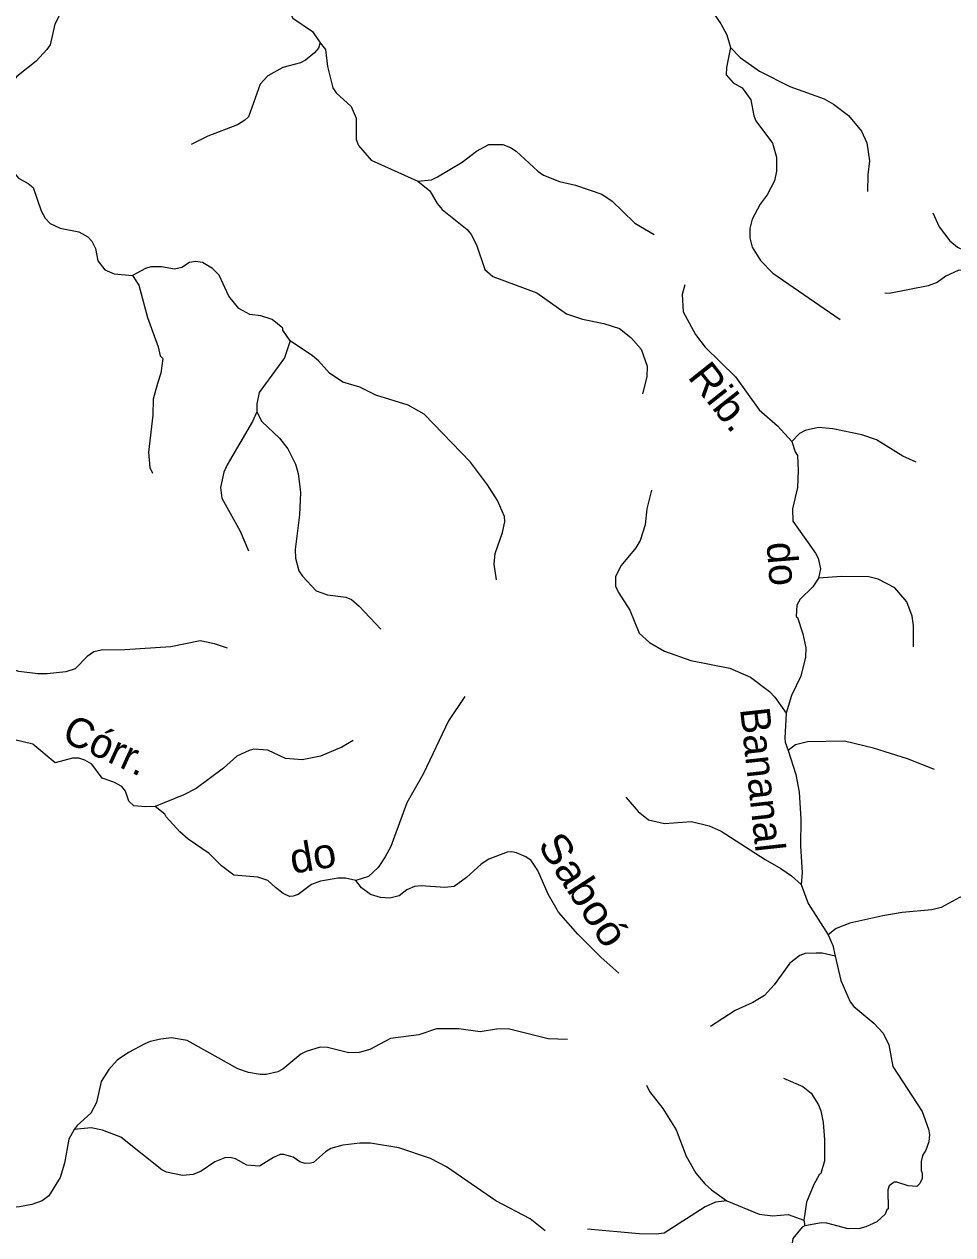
# Model space of a CAD drawing. Extents: x 346.5 to 372.4, y 7400.3 to 7428.2.
# Drawn here: x 350.684 to 353.197, y 7415.488 to 7418.764 of the extents above; entities that cross this region are included whole.
import ezdxf
from ezdxf.enums import TextEntityAlignment as Align

# ---------------------------------------------------------------- set-up
doc = ezdxf.new("R2010")
doc.units = 0
doc.header["$LTSCALE"] = 0.032
doc.layers.add('61', color=7, linetype='Continuous')
doc.layers.add('7', color=7, linetype='Continuous', lineweight=25)

msp = doc.modelspace()

# ---------------------------------------------------------------- linework, layer by layer
at = {"layer": '7'}
for points in [[(350.897, 7418.9228), (350.8692, 7418.8949), (350.8469, 7418.8614), (350.8102, 7418.8312), (350.7911, 7418.8089), (350.7672, 7418.7642), (350.7544, 7418.7085), (350.7457, 7418.6957), (350.717, 7418.6638), (350.6644, 7418.6224), (350.6125, 7418.5604)], [(351.3435, 7418.9146), (351.3768, 7418.8631), (351.3936, 7418.8121), (351.4119, 7418.7802), (351.4645, 7418.7443), (351.4854, 7418.7136)], [(352.4758, 7418.8902), (352.534, 7418.8176), (352.5699, 7418.765), (352.5858, 7418.7355), (352.5963, 7418.7009)], [(351.4854, 7418.7136), (351.4807, 7418.6989), (351.4701, 7418.6861), (351.4454, 7418.6662), (351.4319, 7418.6598), (351.3848, 7418.6471), (351.3442, 7418.624), (351.3227, 7418.6017), (351.2916, 7418.5132), (351.2812, 7418.5044), (351.2621, 7418.4917), (351.1816, 7418.4606), (351.1362, 7418.4383)], [(351.4854, 7418.7136), (351.4999, 7418.695), (351.5052, 7418.6495), (351.5195, 7418.5921), (351.5291, 7418.5778), (351.5689, 7418.5411), (351.5833, 7418.5092), (351.5825, 7418.4518), (351.5888, 7418.4359), (351.6231, 7418.396), (351.7501, 7418.3396)], [(352.5963, 7418.7009), (352.585, 7418.6463), (352.5842, 7418.6272), (352.6033, 7418.6056), (352.6273, 7418.5913), (352.6512, 7418.5594), (352.6591, 7418.5156), (352.6647, 7418.5028), (352.7093, 7418.4423), (352.7205, 7418.404), (352.7205, 7418.3658), (352.7149, 7418.3403), (352.695, 7418.302), (352.6759, 7418.2773), (352.6544, 7418.2367), (352.648, 7418.2112), (352.648, 7418.1857), (352.6544, 7418.1602), (352.6775, 7418.1243), (352.7101, 7418.09), (352.8927, 7417.9649)], [(352.5963, 7418.7009), (352.6225, 7418.6734), (352.6743, 7418.6367), (352.7564, 7418.5953), (352.8496, 7418.5618), (352.8751, 7418.5475), (352.9157, 7418.5172), (352.95, 7418.4742), (352.9652, 7418.4431), (352.9723, 7418.3945), (352.9676, 7418.3562), (352.9668, 7418.3108)], [(350.4957, 7418.4446), (350.5214, 7418.4418), (350.5369, 7418.4359), (350.5616, 7418.4207), (350.6206, 7418.396), (350.6381, 7418.3849), (350.6692, 7418.3474), (350.6955, 7418.3331), (350.709, 7418.3219), (350.7305, 7418.259), (350.7409, 7418.239), (350.7544, 7418.2247), (350.7815, 7418.2119), (350.8326, 7418.2024), (350.8565, 7418.1888), (350.8676, 7418.1769), (350.8772, 7418.157), (350.8835, 7418.1235), (350.9027, 7418.0988), (350.9282, 7418.0884), (350.9779, 7418.0837)], [(351.7501, 7418.3396), (351.7866, 7418.3424), (351.8032, 7418.3506), (351.8694, 7418.3905), (351.9084, 7418.4207), (351.9419, 7418.4383), (351.9801, 7418.4383), (352.0009, 7418.4303), (352.016, 7418.4199), (352.0742, 7418.3658), (352.0901, 7418.3554), (352.1332, 7418.3387), (352.1762, 7418.3283), (352.2479, 7418.3044), (352.2758, 7418.2853), (352.3037, 7418.2582), (352.3372, 7418.2255), (352.389, 7418.1944)], [(351.7501, 7418.3396), (351.7825, 7418.3132), (351.8024, 7418.2789), (351.8152, 7418.2629), (351.8829, 7418.2088), (351.8941, 7418.1952), (351.9084, 7418.1665), (351.9307, 7418.1004), (351.9531, 7418.0812), (352.0718, 7418.0374), (352.1523, 7417.98), (352.1953, 7417.9657), (352.2527, 7417.9537), (352.2957, 7417.9402), (352.326, 7417.9163), (352.3539, 7417.8844), (352.3706, 7417.8382), (352.3698, 7417.8095), (352.3579, 7417.7641)], [(353.1437, 7418.2534), (353.1604, 7418.2159), (353.1899, 7418.1777), (353.2106, 7418.1609), (353.2258, 7418.153), (353.2298, 7418.1474), (353.2545, 7418.1354), (353.2648, 7418.1259), (353.2637, 7418.1236), (353.2785, 7418.0991), (353.282, 7418.0853)], [(351.4041, 7417.9075), (351.384, 7417.9362), (351.384, 7417.941), (351.3553, 7417.9649), (351.3251, 7417.9752), (351.2948, 7417.9784), (351.2653, 7417.9944), (351.2382, 7418.0279), (351.2119, 7418.0844), (351.1944, 7418.1028), (351.1673, 7418.1195), (351.1481, 7418.1219), (351.1322, 7418.1195), (351.1115, 7418.1052), (351.0908, 7418.1012), (351.0557, 7418.1075), (351.027, 7418.1075), (351.0127, 7418.1028), (350.9779, 7418.0837)], [(353.282, 7418.0853), (353.2585, 7418.0932), (353.2282, 7418.0956), (353.2274, 7418.0988), (353.2122, 7418.0972), (353.1788, 7418.082), (353.1549, 7418.0653), (353.1309, 7418.0557), (353.0257, 7418.035), (353.0138, 7418.0358)], [(350.9779, 7418.0837), (350.9943, 7418.0581), (351.0182, 7417.9705), (351.0469, 7417.8908), (351.0525, 7417.8668), (351.0597, 7417.8597), (351.0541, 7417.8199), (351.0453, 7417.792), (351.0334, 7417.7489), (351.0326, 7417.7059), (351.0206, 7417.6055), (351.0246, 7417.564), (351.0318, 7417.5489)], [(352.4727, 7418.0589), (352.4655, 7418.0326), (352.4679, 7417.9856), (352.5013, 7417.9243), (352.5276, 7417.89), (352.6097, 7417.8095), (352.6735, 7417.7202), (352.7229, 7417.6772), (352.7621, 7417.6344)], [(351.4041, 7417.9075), (351.3888, 7417.8613), (351.3203, 7417.7673), (351.3139, 7417.7362), (351.3142, 7417.7153)], [(351.9626, 7417.2604), (351.9562, 7417.3026), (351.9594, 7417.3313), (351.9793, 7417.3887), (351.9849, 7417.4174), (351.9841, 7417.4317), (351.965, 7417.4748), (351.9379, 7417.5178), (351.8925, 7417.5784), (351.7666, 7417.7091), (351.7235, 7417.733), (351.6359, 7417.7601), (351.5928, 7417.7816), (351.5466, 7417.7951), (351.5107, 7417.8199), (351.4805, 7417.8533), (351.4645, 7417.8661), (351.4041, 7417.9075)], [(351.3142, 7417.7153), (351.3019, 7417.6884), (351.2342, 7417.572), (351.2246, 7417.5513), (351.2159, 7417.5098), (351.2191, 7417.4812), (351.2693, 7417.3919), (351.2916, 7417.3385)], [(351.3142, 7417.7153), (351.3274, 7417.6892), (351.3753, 7417.6437), (351.3976, 7417.615), (351.4191, 7417.5736), (351.4255, 7417.5481), (351.4318, 7417.4971), (351.4294, 7417.4365), (351.4175, 7417.3425), (351.4191, 7417.3186), (351.4279, 7417.2851), (351.4374, 7417.27), (351.4749, 7417.2309), (351.5052, 7417.2197), (351.5546, 7417.2134), (351.5705, 7417.207), (351.5912, 7417.1895), (351.6494, 7417.1265)], [(353.0983, 7417.5784), (353.0624, 7417.5951), (352.9907, 7417.6389), (352.9516, 7417.6525), (352.8727, 7417.6692), (352.8345, 7417.6724), (352.7978, 7417.6644), (352.7827, 7417.6565), (352.7621, 7417.6344)], [(352.7621, 7417.6344), (352.7707, 7417.6071), (352.7771, 7417.5967), (352.7787, 7417.5561), (352.7771, 7417.5098), (352.7635, 7417.4525), (352.7643, 7417.419), (352.8257, 7417.3329), (352.8329, 7417.3186), (352.8392, 7417.2899), (352.8341, 7417.2646)], [(352.3818, 7417.5027), (352.3698, 7417.4525), (352.3651, 7417.4094), (352.3515, 7417.3664), (352.3396, 7417.3473), (352.2997, 7417.2995), (352.2846, 7417.2692), (352.2846, 7417.2436), (352.2925, 7417.2261), (352.3236, 7417.1783), (352.3491, 7417.1162), (352.377, 7417.0906), (352.4169, 7417.0675), (352.4886, 7417.042), (352.5938, 7417.0213), (352.6496, 7416.9974), (352.7014, 7416.9583), (352.7157, 7416.9432), (352.7465, 7416.8998)], [(352.8341, 7417.2646), (352.8185, 7417.2413), (352.7843, 7417.2078), (352.7755, 7417.1919), (352.7739, 7417.1608), (352.7771, 7417.1584), (352.7914, 7417.1146), (352.7994, 7417.0763), (352.7986, 7417.0508), (352.7859, 7416.9998), (352.7611, 7416.9472), (352.7465, 7416.8998)], [(353.0911, 7417.0787), (353.0911, 7417.1369), (353.0879, 7417.1624), (353.0728, 7417.2006), (353.0409, 7417.2389), (352.9955, 7417.262), (352.97, 7417.2684), (352.8966, 7417.2692), (352.8341, 7417.2646)], [(351.235, 7417.0755), (351.1991, 7417.0875), (351.1609, 7417.0954), (351.0812, 7417.0795), (350.9569, 7417.0707), (350.8931, 7417.0699), (350.8732, 7417.0659), (350.8548, 7417.0532), (350.8222, 7417.0197), (350.7975, 7417.0117), (350.7465, 7417.0062), (350.721, 7417.0062), (350.67, 7417.0125), (350.65, 7417.0189), (350.6318, 7417.0351)], [(351.8773, 7416.9448), (351.8327, 7416.8787), (351.765, 7416.7368), (351.7203, 7416.6571), (351.6765, 7416.5392), (351.6614, 7416.5105), (351.6422, 7416.4818), (351.616, 7416.458), (351.5821, 7416.4471)], [(352.7465, 7416.8998), (352.7428, 7416.8324), (352.7436, 7416.8213), (352.7523, 7416.799)], [(351.0389, 7416.6472), (351.0127, 7416.6459), (350.9808, 7416.6491), (350.9672, 7416.6619), (350.9585, 7416.6882), (350.9489, 7416.7009), (350.9266, 7416.7129), (350.8955, 7416.7241), (350.8676, 7416.7615), (350.8485, 7416.7727), (350.8326, 7416.7774), (350.815, 7416.7782), (350.768, 7416.7655), (350.7082, 7416.8157), (350.6588, 7416.8276), (350.6432, 7416.8406)], [(351.5745, 7416.8261), (351.5442, 7416.8077), (351.486, 7416.783), (351.4366, 7416.7735), (351.392, 7416.7766), (351.3442, 7416.7998), (351.3059, 7416.8021), (351.2932, 7416.799), (351.2597, 7416.783), (351.2238, 7416.7511), (351.1497, 7416.6954), (351.1163, 7416.6786), (351.0389, 7416.6472)], [(353.1477, 7416.7472), (353.0752, 7416.7759), (352.9827, 7416.8053), (352.9046, 7416.8237), (352.8042, 7416.8221), (352.7717, 7416.8138), (352.7523, 7416.799)], [(352.7523, 7416.799), (352.7731, 7416.7336), (352.7819, 7416.6858), (352.7859, 7416.6125), (352.7851, 7416.5408), (352.7898, 7416.4674), (352.7874, 7416.4356)], [(352.3125, 7416.6723), (352.3459, 7416.6332), (352.3738, 7416.6109), (352.4169, 7416.6013), (352.4902, 7416.6061), (352.538, 7416.5949), (352.5707, 7416.5806), (352.6894, 7416.5033), (352.7325, 7416.4794), (352.7612, 7416.4594), (352.7874, 7416.4356)], [(351.5821, 7416.4471), (351.5538, 7416.4531), (351.5339, 7416.4531), (351.486, 7416.4451), (351.4621, 7416.4363), (351.4255, 7416.4093), (351.4127, 7416.4045), (351.4024, 7416.4037), (351.3856, 7416.4116), (351.3649, 7416.4276), (351.3442, 7416.4467), (351.3171, 7416.4555), (351.2517, 7416.461), (351.2183, 7416.4866), (351.1848, 7416.52), (351.1282, 7416.5591), (351.1059, 7416.5782), (351.0684, 7416.6189), (351.0652, 7416.626), (351.0389, 7416.6472)], [(352.2934, 7416.1957), (352.2447, 7416.2395), (352.1826, 7416.3017), (352.1308, 7416.3614), (352.1021, 7416.4101), (352.0742, 7416.4738), (352.0567, 7416.5009), (352.0423, 7416.5113), (352.0168, 7416.5216), (352.0041, 7416.5248), (351.9913, 7416.5232), (351.9419, 7416.5049), (351.9212, 7416.4913), (351.8813, 7416.4547), (351.8479, 7416.4308), (351.8224, 7416.4276), (351.7586, 7416.4324), (351.7403, 7416.4308), (351.7203, 7416.4212), (351.6996, 7416.4053), (351.6741, 7416.3989), (351.6486, 7416.4005), (351.6215, 7416.4093), (351.5972, 7416.4271), (351.5821, 7416.4471)], [(352.7874, 7416.4356), (352.8058, 7416.3846), (352.8598, 7416.2999)], [(353.2513, 7416.414), (353.2154, 7416.4005), (353.166, 7416.3742), (353.1405, 7416.3678), (353.0608, 7416.3598), (353.0082, 7416.3511), (352.919, 7416.3311), (352.8816, 7416.3165), (352.8598, 7416.2999)], [(352.8598, 7416.2999), (352.8727, 7416.2706), (352.8793, 7416.2418)], [(352.8793, 7416.2418), (352.844, 7416.2499), (352.8281, 7416.2506), (352.7978, 7416.2491), (352.7835, 7416.2435), (352.7564, 7416.2228), (352.7141, 7416.1646), (352.6878, 7416.1359), (352.656, 7416.1168), (352.6081, 7416.0953), (352.542, 7416.0514)], [(352.8793, 7416.2418), (352.8942, 7416.1758), (352.9197, 7416.1184), (352.9301, 7416.1056), (352.9835, 7416.061), (353.009, 7416.0339), (353.0241, 7416.002), (353.0353, 7415.9431), (353.115, 7415.8219), (353.1317, 7415.7741), (353.1341, 7415.7598), (353.1325, 7415.7398), (353.1245, 7415.7167), (353.1158, 7415.7024), (353.1118, 7415.6864), (353.1118, 7415.6617), (353.115, 7415.6546), (353.1142, 7415.6402), (353.1086, 7415.6267), (353.0999, 7415.6187), (353.0768, 7415.6203), (353.0465, 7415.6306), (353.0385, 7415.6306), (353.0257, 7415.6203), (353.0217, 7415.6099), (353.0225, 7415.5581), (353.0186, 7415.5557), (353.0146, 7415.5438), (352.9915, 7415.5231), (352.962, 7415.5095), (352.9461, 7415.5055), (352.9142, 7415.5047), (352.8568, 7415.5199), (352.8424, 7415.5207), (352.7974, 7415.5127)], [(352.1547, 7416.0164), (352.1029, 7416.0187), (351.9945, 7416.045), (351.9626, 7416.0442), (351.918, 7416.0371), (351.8606, 7416.045), (351.8, 7416.045), (351.7522, 7416.0291), (351.6757, 7416.0195), (351.6199, 7415.9893), (351.5912, 7415.9813), (351.5626, 7415.9805), (351.5052, 7415.9948), (351.4852, 7415.9956), (351.4478, 7415.9845), (351.4334, 7415.9765), (351.3848, 7415.9367), (351.3713, 7415.9295), (351.3394, 7415.9215), (351.3235, 7415.9215), (351.2916, 7415.9271), (351.2629, 7415.9375), (351.1258, 7416.014), (351.0828, 7416.0211), (351.0541, 7416.0179), (351.0254, 7416.0116), (351.0111, 7416.0052), (350.9664, 7415.9813), (350.9361, 7415.9606), (350.9138, 7415.9351), (350.8931, 7415.9032), (350.8804, 7415.8458), (350.8644, 7415.8171), (350.828, 7415.7842), (350.8198, 7415.7732)], [(352.7394, 7415.9116), (352.7914, 7415.8896), (352.8138, 7415.8713), (352.8337, 7415.8394), (352.84, 7415.8235), (352.8464, 7415.7916), (352.8504, 7415.7454), (352.8504, 7415.688), (352.8408, 7415.6538), (352.8361, 7415.6506), (352.8217, 7415.6243), (352.8018, 7415.5765), (352.7941, 7415.528), (352.7974, 7415.5127)], [(352.3683, 7415.8928), (352.377, 7415.8761), (352.4129, 7415.8299), (352.4487, 7415.7725), (352.4758, 7415.7008), (352.5021, 7415.6553), (352.5268, 7415.6258), (352.5444, 7415.6099), (352.5863, 7415.58)], [(350.8198, 7415.7732), (350.8054, 7415.747), (350.7935, 7415.6817), (350.7815, 7415.6434), (350.7513, 7415.594), (350.7329, 7415.5796), (350.705, 7415.5701), (350.6716, 7415.5637), (350.6269, 7415.5597), (350.6046, 7415.5613), (350.5823, 7415.5573), (350.56, 7415.5462), (350.5416, 7415.525)], [(352.0941, 7415.4992), (352.0535, 7415.531), (351.961, 7415.5804), (351.8271, 7415.6721), (351.7841, 7415.6944), (351.698, 7415.7231), (351.6215, 7415.7358), (351.5928, 7415.7358), (351.5466, 7415.7303), (351.5147, 7415.7215), (351.4996, 7415.7127), (351.4677, 7415.684), (351.459, 7415.6816), (351.4446, 7415.6808), (351.4303, 7415.6856), (351.4127, 7415.6984), (351.3872, 7415.7055), (351.3776, 7415.7055), (351.3593, 7415.6976), (351.3211, 7415.6737), (351.2868, 7415.6769), (351.2565, 7415.6936), (351.2422, 7415.6976), (351.2278, 7415.696), (351.2007, 7415.6856), (351.1633, 7415.6601), (351.1418, 7415.6514), (351.1131, 7415.6482), (351.07, 7415.6577), (351.0565, 7415.6641), (350.9457, 7415.7526), (350.8963, 7415.7709), (350.866, 7415.7773), (350.8198, 7415.7732)], [(352.5863, 7415.58), (352.5555, 7415.5764), (352.5277, 7415.5637), (352.4161, 7415.4928), (352.3946, 7415.4896), (352.3483, 7415.4904), (352.2089, 7415.5031)], [(352.5863, 7415.58), (352.6735, 7415.5438), (352.7102, 7415.5398), (352.7524, 7415.543), (352.7941, 7415.528)], [(352.7974, 7415.5127), (352.7899, 7415.5086), (352.7643, 7415.4784), (352.7603, 7415.4474), (352.7691, 7415.4203), (352.7954, 7415.3876), (352.8265, 7415.3581), (352.8353, 7415.3437), (352.8472, 7415.3087), (352.8512, 7415.2529), (352.8711, 7415.2091), (352.8879, 7415.1915), (352.9253, 7415.1812), (352.9508, 7415.182), (353.0146, 7415.2051), (353.0257, 7415.2051), (353.0528, 7415.2035), (353.06, 7415.1995), (353.0768, 7415.1899), (353.0937, 7415.1731)]]:
    msp.add_lwpolyline(points, dxfattribs=at)

# ---------------------------------------------------------------- texts
at = {"layer": '61'}
for s, rotation, width, p in [('Rib.', 308.416, 1.05, (352.5398, 7417.731)), ('do', 9.78, 1.05, (351.4721, 7416.4753)), ('Saboó', 302.938, 1.1, (352.1646, 7416.4006))]:
    msp.add_text(s, height=0.08, rotation=rotation, dxfattribs=dict(at, width=width)).set_placement(p, align=Align.CENTER)
for s, rotation, p in [('do', 274.443, (352.698, 7417.3009)), ('Córr.', 335.431, (350.8906, 7416.7767)), ('Bananal', 276.229, (352.6429, 7416.716))]:
    msp.add_text(s, height=0.08, rotation=rotation, dxfattribs=at).set_placement(p, align=Align.CENTER)

doc.saveas('drawing.dxf')
